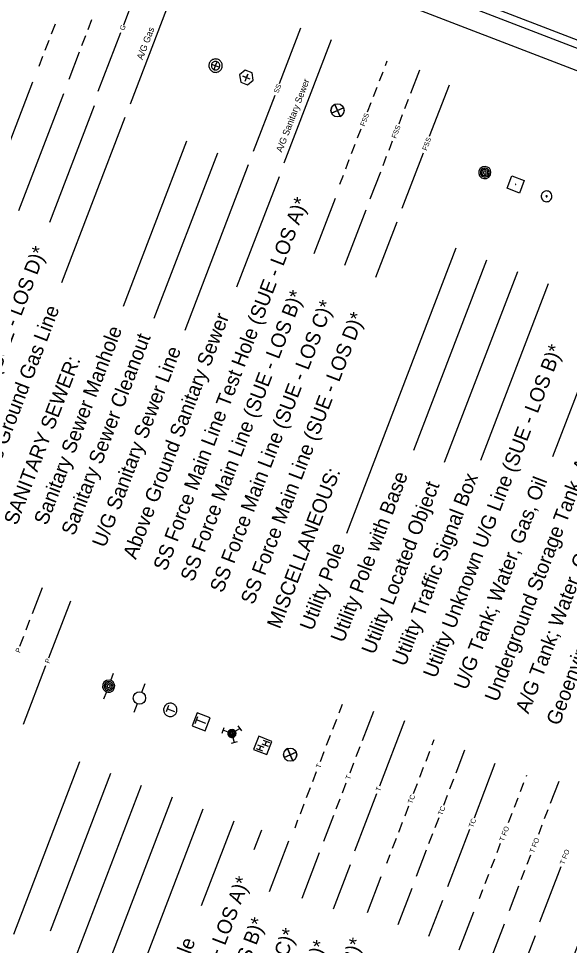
# Model space of a CAD drawing. Extents: x 1015221 to 1064345, y 619216 to 647967.
# Drawn here: x 1051569 to 1054188, y 630539 to 634941 of the extents above; entities that cross this region are included whole.
import ezdxf

# ---------------------------------------------------------------- set-up
doc = ezdxf.new("R2010")
doc.units = 0
for name, color, linetype in [('Default', 7, 'Continuous'), ('Sheet Plot Border Inside CELL', 7, 'Continuous'), ('Sheet Plot Border Outside CELL', 7, 'Continuous'), ('Sheet Symbology CELL', 7, 'Continuous')]:
    doc.layers.add(name, color=color, linetype=linetype)

msp = doc.modelspace()

# ---------------------------------------------------------------- linework, layer by layer
at = {"layer": 'Default'}
for p, q in [((1052069.1, 634911.4), (1052172.7, 635181.1)), ((1052100.4, 634536.4), (1052325.5, 635122.3)), ((1051899.7, 634889.2), (1051918, 634936.8)), ((1051725.7, 634867.8), (1051744, 634915.4)), ((1052809.1, 634632.2), (1052911, 634897.4)), ((1051696.2, 634790.9), (1051714.5, 634838.5)), ((1051870.2, 634812.3), (1051888.5, 634859.9)), ((1051947.5, 634595.1), (1052055, 634874.8)), ((1052831.3, 634255.6), (1053056.4, 634841.5)), ((1051666.6, 634714), (1051684.9, 634761.6)), ((1051809.2, 634653.5), (1051858.9, 634783)), ((1052486.7, 634724.2), (1052524.3, 634709.8)), ((1052498.3, 634698.2), (1052505.5, 634717)), ((1052504.6, 634714.6), (1052504.7, 634714.8)), ((1052505.5, 634717), (1052512.7, 634735.8)), ((1053312.6, 634717.7), (1053321.1, 634739.8)), ((1053284.4, 634644.4), (1053301.3, 634688.4)), ((1053433.9, 634587), (1053476, 634696.7)), ((1051635.6, 634639.2), (1051422.5, 634084.5)), ((1053522.8, 634381.4), (1053616.9, 634626.2)), ((1051782.1, 634582.9), (1051568.9, 634028.2)), ((1052685.9, 634311.5), (1052788, 634577.2)), ((1053256.3, 634571.2), (1053273.2, 634615.1)), ((1053228.1, 634498), (1053245, 634541.9)), ((1053405.7, 634513.8), (1053422.6, 634557.7)), ((1051928.6, 634526.7), (1051715.4, 633971.9)), ((1053377.6, 634440.5), (1053394.5, 634484.5)), ((1052075, 634470.4), (1051773.3, 633685)), ((1053180.3, 634373.5), (1053197.2, 634417.4)), ((1052367.6, 634358), (1052065.8, 633572.6)), ((1053329.8, 634316), (1053346.6, 634360)), ((1053152.2, 634300.2), (1053169, 634344.2)), ((1052514.1, 634301.7), (1052212.3, 633516.3)), ((1053124, 634227), (1053140.9, 634270.9)), ((1053301.6, 634242.8), (1053318.5, 634286.7)), ((1053391.8, 634040.3), (1053493, 634303.7)), ((1052660.5, 634245.4), (1052358.8, 633460)), ((1052807, 634189.2), (1052605.4, 633664.4)), ((1053095.9, 634153.9), (1053112.8, 634197.7)), ((1053241, 634085.1), (1053290.4, 634213.5)), ((1053073.6, 634086.8), (1052972.4, 633823.5)), ((1053220, 634030.5), (1053118.9, 633767.3)), ((1053366.5, 633974.2), (1053265.4, 633711)), ((1053647.3, 633850.3), (1053127, 632495.9)), ((1053793.8, 633794), (1053446.1, 632889.2)), ((1053940.3, 633737.7), (1053592.6, 632832.9)), ((1054086.7, 633681.4), (1053764.1, 632841.5)), ((1054379.7, 633568.9), (1054106.9, 632858.7)), ((1051634.6, 632114.8), (1051682.5, 632239.5)), ((1051713.5, 631905.4), (1051817.4, 632175.7)), ((1051605.1, 632037.9), (1051623.4, 632085.5)), ((1051575.5, 631961), (1051593.8, 632008.6)), ((1051592.2, 631589.8), (1051699.4, 631868.7)), ((1052007.6, 631797.4), (1052021.1, 631832.6)), ((1052154.5, 631741.8), (1052170.3, 631783)), ((1051986.9, 631743.3), (1051973.4, 631708.2)), ((1052133.4, 631686.9), (1052117.5, 631645.7)), ((1052282.3, 631678.3), (1052270.7, 631648.1)), ((1053092.5, 631643.5), (1053108.1, 631684.4)), ((1052276.4, 631663.1), (1052309.7, 631650.3)), ((1052408, 631592.9), (1052421.2, 631627.2)), ((1053203.5, 631512.6), (1053257.1, 631652.1)), ((1052458.8, 631593.1), (1052414.6, 631610)), ((1052611.7, 631582.3), (1052628.2, 631557.9)), ((1053062.9, 631566.6), (1053081.2, 631614.2)), ((1053286.1, 631297.6), (1053405.4, 631608)), ((1052536.5, 631547.5), (1052547, 631574.9)), ((1052565.2, 631552.2), (1052541.7, 631561.2)), ((1052599.1, 631556.1), (1052620, 631570.1)), ((1053033.4, 631489.7), (1053051.7, 631537.3)), ((1052608.2, 631505.8), (1052579.6, 631498.7)), ((1052587.8, 631526.6), (1052593.9, 631502.2)), ((1052705.4, 631491.9), (1052734.9, 631480.6)), ((1052725.8, 631497), (1052755.3, 631485.7)), ((1052732.3, 631513.9), (1052761.8, 631502.6)), ((1052740.8, 631491.3), (1052747.3, 631508.1)), ((1053535.3, 631491.6), (1053544.9, 631516.6)), ((1052698.9, 631475.1), (1052728.4, 631463.7)), ((1052713.9, 631469.3), (1052720.4, 631486.1)), ((1053003.8, 631412.8), (1053022.1, 631460.4)), ((1053174, 631435.7), (1053192.3, 631483.3)), ((1053505.7, 631414.7), (1053524, 631462.3)), ((1053649.1, 631359.6), (1053690.9, 631468.5)), ((1051859.3, 631411.4), (1051544.5, 630591.9)), ((1053144.5, 631358.8), (1053162.7, 631406.4)), ((1053735.4, 631145.7), (1053835.1, 631405.1)), ((1052967.5, 631318.4), (1052985.8, 631366)), ((1053476.2, 631337.8), (1053494.5, 631385.4)), ((1052005.8, 631355.1), (1051718.6, 630607.6)), ((1053619.5, 631282.7), (1053637.8, 631330.3)), ((1053982.5, 631342.9), (1053984.4, 631347.7)), ((1054097.7, 631214.6), (1054138, 631319.4)), ((1052152.3, 631298.8), (1051764.4, 630289.1)), ((1052938, 631241.4), (1052956.3, 631289.1)), ((1053108.2, 631264.3), (1053126.4, 631311.9)), ((1053446.6, 631260.9), (1053464.9, 631308.5)), ((1053954.4, 631269.6), (1053971.3, 631313.6)), ((1052298.8, 631242.6), (1051912.8, 630238)), ((1053078.6, 631187.4), (1053096.9, 631235)), ((1053167.6, 630989.1), (1053272.1, 631261)), ((1053590, 631205.8), (1053608.3, 631253.4)), ((1053926.2, 631196.4), (1053943.1, 631240.3)), ((1052445.3, 631186.3), (1052092.9, 630269.1)), ((1052908.4, 631164.5), (1052926.7, 631212.2)), ((1053405.8, 631154.7), (1053424.1, 631202.3)), ((1054069.5, 631141.3), (1054086.4, 631185.3)), ((1053020.1, 631035.2), (1053067.3, 631158.1)), ((1053549.2, 631099.6), (1053567.5, 631147.2)), ((1053898.1, 631123.1), (1053915, 631167.1)), ((1052591.7, 631130), (1052436.9, 630726.9)), ((1052883, 631098.4), (1052897.2, 631135.2)), ((1053376.3, 631077.8), (1053394.6, 631125.4)), ((1054041.4, 631068.1), (1054058.3, 631112)), ((1052723.5, 631086.3), (1052687.9, 630993.6)), ((1053519.6, 631022.7), (1053537.9, 631070.3)), ((1053610, 630819.2), (1053714.3, 631090.8)), ((1052851.8, 631034.7), (1052759.6, 630794.6)), ((1053346.7, 631000.9), (1053365, 631048.5)), ((1053843.2, 630980.3), (1053860.1, 631024.3)), ((1052998.3, 630978.4), (1052914.9, 630761.4)), ((1053319.8, 630930.6), (1053335.5, 630971.6)), ((1053460.4, 630868.6), (1053508.4, 630993.4)), ((1053986.5, 630925.3), (1054003.4, 630969.2)), ((1053144.8, 630922.1), (1053063.6, 630710.8)), ((1053815.1, 630907.1), (1053832, 630951)), ((1053787, 630833.8), (1053803.8, 630877.8)), ((1053958.4, 630852), (1053975.3, 630896)), ((1054046.6, 630651.4), (1054147.6, 630914.1)), ((1053291.3, 630865.8), (1053225.2, 630694)), ((1053437.8, 630809.6), (1053371.7, 630637.7)), ((1053759.3, 630761.8), (1053775.7, 630804.5)), ((1053902.1, 630705.4), (1053947.1, 630822.7)), ((1053584.2, 630753.3), (1053518.2, 630581.4)), ((1053730.7, 630697), (1053661.4, 630516.6)), ((1053877.2, 630640.7), (1053807.9, 630460.4)), ((1054023.7, 630584.4), (1053954.4, 630404.1))]:
    msp.add_line(p, q, dxfattribs=at)
for points in [[(1052475.8, 634728.4), (1052474.5, 634724.5), (1052473.9, 634720.7), (1052473.7, 634716.6), (1052474.1, 634712.7), (1052474.8, 634708.8), (1052476.1, 634705.1), (1052477.9, 634701.4), (1052480, 634698.1), (1052482.5, 634694.9), (1052485.7, 634692.4), (1052488.9, 634690.1), (1052492.3, 634688.2), (1052496.1, 634686.8), (1052499.8, 634685.9), (1052504, 634685.3), (1052507.8, 634685.2), (1052511.8, 634685.9), (1052515.5, 634686.9), (1052519.4, 634688.4), (1052522.8, 634690.4), (1052525.9, 634692.7), (1052528.9, 634695.4), (1052531.4, 634698.5), (1052533.6, 634702.1), (1052535.2, 634705.6), (1052536.4, 634709.5), (1052537.1, 634713.3), (1052537.3, 634717.3), (1052536.9, 634721.3), (1052536.2, 634725.1), (1052534.9, 634728.9), (1052533.1, 634732.6), (1052531, 634735.8), (1052528.4, 634739), (1052525.3, 634741.6), (1052522.1, 634743.9), (1052518.7, 634745.7), (1052514.9, 634747.2), (1052511.2, 634748.1), (1052507, 634748.6), (1052503.2, 634748.7), (1052499.1, 634748.1), (1052495.5, 634747), (1052491.6, 634745.5), (1052488.1, 634743.6), (1052485, 634741.2), (1052482.1, 634738.5), (1052479.5, 634735.4), (1052477.4, 634731.9), (1052475.8, 634728.4)], [(1052486.7, 634724.2), (1052485.7, 634721), (1052485.4, 634717.9), (1052485.5, 634714.6), (1052486.2, 634711.6), (1052487.2, 634708.4), (1052488.8, 634705.6), (1052490.9, 634703.2), (1052493.3, 634700.9), (1052496, 634699.3), (1052499, 634697.9), (1052502.3, 634697.2), (1052505.4, 634696.8), (1052508.8, 634697.1), (1052511.8, 634697.9), (1052514.8, 634699.2), (1052517.6, 634700.9), (1052520, 634702.9), (1052522.1, 634705.4), (1052523.7, 634708.3), (1052524.8, 634711.2), (1052525.5, 634714.5), (1052525.7, 634717.7), (1052525.3, 634720.8), (1052524.3, 634724), (1052523, 634726.9), (1052521.2, 634729.5), (1052518.9, 634732), (1052516.3, 634733.8), (1052513.4, 634735.5), (1052510.2, 634736.5), (1052507.2, 634737.1), (1052503.9, 634737), (1052500.7, 634736.6), (1052497.6, 634735.6), (1052494.8, 634733.9), (1052492.2, 634732.2), (1052489.9, 634729.8), (1052488.1, 634727.2), (1052486.7, 634724.2)], [(1052684.4, 634648.2), (1052679.2, 634682.7), (1052646.5, 634695.3), (1052619.5, 634673.2), (1052625, 634638.6), (1052657.5, 634626.1), (1052684.4, 634648.2)], [(1052645.6, 634644.1), (1052658.4, 634677.3), (1052652, 634660.7), (1052635.4, 634667.1), (1052668.6, 634654.3)], [(1053072.5, 634533.3), (1053097.9, 634476), (1053085.2, 634504.6), (1053056.6, 634491.9), (1053113.9, 634517.4)], [(1053056.6, 634491.9), (1053085.2, 634504.6), (1053072.5, 634533.3)], [(1053113.9, 634517.4), (1053085.2, 634504.6), (1053097.9, 634476)], [(1053792.9, 634229.2), (1053787.8, 634230.6), (1053782.9, 634230.6), (1053778.1, 634229.4), (1053773.6, 634227.3), (1053769.9, 634224.4), (1053767, 634219.9), (1053764.8, 634215.8), (1053764, 634210.6), (1053764, 634205.6), (1053765.4, 634201.3), (1053768, 634196.6), (1053770.9, 634193), (1053775.4, 634190), (1053779.7, 634188.4), (1053785, 634187.6), (1053789.6, 634188.3), (1053794.6, 634190.1), (1053798.6, 634192.3), (1053801.9, 634196), (1053804.8, 634200.5), (1053805.9, 634205), (1053806.7, 634210.3), (1053806, 634214.9), (1053804, 634219.4), (1053801.3, 634223.5), (1053797.6, 634226.8), (1053792.9, 634229.2)], [(1053790.4, 634222.7), (1053786.4, 634223.7), (1053782, 634223.5), (1053778.3, 634221.8), (1053774.9, 634219.4), (1053772.5, 634216.6), (1053770.9, 634212.3), (1053770.7, 634208.6), (1053771.6, 634204.5), (1053773.3, 634200.8), (1053776.4, 634197.7), (1053780, 634195.7), (1053784, 634194.8), (1053788.4, 634195), (1053792.2, 634196.6), (1053795.6, 634199), (1053797.9, 634201.9), (1053799.6, 634206.2), (1053799.7, 634209.9), (1053798.8, 634213.9), (1053797.1, 634217.7), (1053794, 634220.8), (1053790.4, 634222.7)], [(1053787.7, 634215.7), (1053784.8, 634216.2), (1053782, 634215.4), (1053780.1, 634213.7), (1053778.5, 634211.2), (1053778.6, 634208.1), (1053779.3, 634205.3), (1053781.6, 634203.2), (1053783.8, 634202.3), (1053786.9, 634202.4), (1053789.4, 634203.9), (1053791.5, 634206.2), (1053792, 634209.1), (1053791.7, 634211.7), (1053790.2, 634214.1), (1053787.7, 634215.7)], [(1053890.8, 634134.5), (1053913.5, 634193.8), (1053972.8, 634171), (1053950, 634111.7), (1053890.8, 634134.5)], [(1053931, 634152.9), (1053931.2, 634152.5), (1053931.8, 634152.3), (1053932.6, 634152.6), (1053932.5, 634153.3), (1053932, 634153.8), (1053931.2, 634153.5), (1053931, 634152.9)], [(1054087.8, 634120.3), (1054082.9, 634121.6), (1054077.6, 634122), (1054072.4, 634121.3), (1054067.7, 634119.3), (1054063.4, 634116.5), (1054059.4, 634113.2), (1054056.8, 634109.3), (1054054.3, 634104.2), (1054053.4, 634099.1), (1054053.2, 634094.3), (1054054, 634089.1), (1054056, 634084.4), (1054059.2, 634079.9), (1054062.8, 634076.4), (1054067.1, 634073.6), (1054071.9, 634071.8), (1054077, 634070.9), (1054082, 634071.2), (1054087.4, 634072.4), (1054092, 634074.4), (1054096.1, 634077.8), (1054099.1, 634081.5), (1054101.9, 634085.9), (1054103.4, 634091.3), (1054104.1, 634096), (1054103.4, 634101.2), (1054102, 634106.1), (1054099.9, 634110.7), (1054096.6, 634114.7), (1054092.4, 634118), (1054087.8, 634120.3)], [(1054076.2, 634098.5), (1054075.6, 634097.1), (1054076, 634095.3), (1054077.1, 634093.8), (1054078.7, 634093.7), (1054080.5, 634094.1), (1054081.5, 634095.4), (1054081.6, 634097), (1054081, 634098.3), (1054079.3, 634099.5), (1054077.7, 634099.6), (1054076.2, 634098.5)], [(1052004.9, 631790.4), (1051999.9, 631791.7), (1051994.9, 631791.8), (1051990.1, 631790.5), (1051985.6, 631788.5), (1051982, 631785.6), (1051979, 631781.1), (1051976.8, 631777), (1051976, 631771.7), (1051976, 631766.8), (1051977.5, 631762.5), (1051980, 631757.8), (1051983, 631754.2), (1051987.4, 631751.2), (1051991.7, 631749.5), (1051997, 631748.8), (1052001.6, 631749.5), (1052006.7, 631751.3), (1052010.6, 631753.5), (1052013.9, 631757.2), (1052016.8, 631761.6), (1052018, 631766.1), (1052018.8, 631771.4), (1052018, 631776), (1052016, 631780.5), (1052013.3, 631784.7), (1052009.6, 631788), (1052004.9, 631790.4)], [(1052002.4, 631783.9), (1051998.4, 631784.8), (1051994, 631784.6), (1051990.3, 631783), (1051986.9, 631780.6), (1051984.6, 631777.7), (1051982.9, 631773.4), (1051982.7, 631769.7), (1051983.6, 631765.7), (1051985.3, 631761.9), (1051988.5, 631758.9), (1051992.1, 631756.9), (1051996.1, 631756), (1052000.4, 631756.1), (1052004.2, 631757.8), (1052007.6, 631760.2), (1052009.9, 631763), (1052011.6, 631767.4), (1052011.8, 631771), (1052010.8, 631775.1), (1052009.2, 631778.8), (1052006, 631781.9), (1052002.4, 631783.9)], [(1051999.7, 631776.9), (1051996.8, 631777.4), (1051994, 631776.6), (1051992.1, 631774.8), (1051990.6, 631772.3), (1051990.6, 631769.2), (1051991.4, 631766.4), (1051993.7, 631764.3), (1051995.8, 631763.5), (1051999, 631763.5), (1052001.4, 631765.1), (1052003.5, 631767.4), (1052004, 631770.3), (1052003.8, 631772.8), (1052002.2, 631775.3), (1051999.7, 631776.9)], [(1052260.5, 631669.2), (1052259.3, 631665.4), (1052258.6, 631661.5), (1052258.4, 631657.5), (1052258.8, 631653.5), (1052259.5, 631649.7), (1052260.8, 631645.9), (1052262.6, 631642.2), (1052264.7, 631639), (1052267.3, 631635.8), (1052270.4, 631633.2), (1052273.6, 631630.9), (1052277, 631629.1), (1052280.8, 631627.6), (1052284.5, 631626.7), (1052288.7, 631626.2), (1052292.5, 631626.1), (1052296.6, 631626.7), (1052300.2, 631627.8), (1052304.1, 631629.3), (1052307.6, 631631.2), (1052310.7, 631633.6), (1052313.6, 631636.3), (1052316.2, 631639.4), (1052318.3, 631642.9), (1052319.9, 631646.4), (1052321.2, 631650.3), (1052321.8, 631654.1), (1052322, 631658.2), (1052321.6, 631662.1), (1052320.9, 631666), (1052319.6, 631669.7), (1052317.8, 631673.4), (1052315.8, 631676.7), (1052313.2, 631679.9), (1052310, 631682.4), (1052306.8, 631684.7), (1052303.5, 631686.6), (1052299.6, 631688.1), (1052295.9, 631689), (1052291.7, 631689.5), (1052287.9, 631689.6), (1052283.9, 631688.9), (1052280.2, 631687.9), (1052276.3, 631686.4), (1052272.9, 631684.4), (1052269.8, 631682.1), (1052266.8, 631679.4), (1052264.3, 631676.3), (1052262.1, 631672.7), (1052260.5, 631669.2)], [(1052455.7, 631558.9), (1052479.4, 631620.5), (1052417.7, 631644.2), (1052394, 631582.6), (1052455.7, 631558.9)], [(1052588.3, 631558.6), (1052584.9, 631559.5), (1052581.6, 631559.5), (1052578.4, 631558.7), (1052575.4, 631557.3), (1052573, 631555.4), (1052571, 631552.4), (1052569.6, 631549.7), (1052569, 631546.1), (1052569, 631542.8), (1052570, 631540), (1052571.7, 631536.9), (1052573.7, 631534.4), (1052576.6, 631532.5), (1052579.5, 631531.4), (1052583, 631530.8), (1052586.1, 631531.3), (1052589.5, 631532.5), (1052592.1, 631534), (1052594.3, 631536.5), (1052596.2, 631539.4), (1052597, 631542.4), (1052597.5, 631546), (1052597, 631549), (1052595.7, 631552), (1052593.9, 631554.8), (1052591.4, 631557), (1052588.3, 631558.6)], [(1052586.6, 631554.3), (1052584, 631554.9), (1052581.1, 631554.8), (1052578.5, 631553.7), (1052576.3, 631552.1), (1052574.7, 631550.2), (1052573.6, 631547.3), (1052573.5, 631544.8), (1052574.1, 631542.1), (1052575.2, 631539.6), (1052577.3, 631537.6), (1052579.7, 631536.3), (1052582.4, 631535.6), (1052585.3, 631535.8), (1052587.8, 631536.9), (1052590.1, 631538.5), (1052591.6, 631540.4), (1052592.7, 631543.2), (1052592.9, 631545.7), (1052592.3, 631548.4), (1052591.1, 631550.9), (1052589, 631552.9), (1052586.6, 631554.3)], [(1052584.8, 631549.6), (1052582.9, 631549.9), (1052581.1, 631549.4), (1052579.8, 631548.2), (1052578.7, 631546.6), (1052578.7, 631544.5), (1052579.3, 631542.6), (1052580.8, 631541.2), (1052582.2, 631540.7), (1052584.3, 631540.7), (1052586, 631541.7), (1052587.4, 631543.2), (1052587.7, 631545.2), (1052587.5, 631546.9), (1052586.5, 631548.5), (1052584.8, 631549.6)], [(1052749.1, 631445.3), (1052773.3, 631508.4), (1052710.3, 631532.6), (1052686, 631469.6), (1052749.1, 631445.3)], [(1052847, 631473.7), (1052872.5, 631416.4), (1052859.8, 631445.1), (1052831.1, 631432.3), (1052888.4, 631457.8)], [(1052831.1, 631432.3), (1052859.8, 631445.1), (1052847, 631473.7)], [(1052888.4, 631457.8), (1052859.8, 631445.1), (1052872.5, 631416.4)]]:
    msp.add_lwpolyline(points, dxfattribs=at)
for points in [[(1053812.3, 634198.8), (1053814.5, 634211), (1053812, 634220.7), (1053806.7, 634229.5), (1053797.2, 634235.6), (1053787.1, 634238.3), (1053775.3, 634236.6), (1053763, 634228.9), (1053757.1, 634216.9), (1053756.2, 634204.9), (1053760.5, 634193.3), (1053769.1, 634185), (1053781, 634180.5), (1053792.9, 634180.8), (1053804.8, 634187.4)], [(1052024.3, 631760), (1052026.5, 631772.2), (1052024, 631781.8), (1052018.7, 631790.7), (1052009.3, 631796.8), (1051999.1, 631799.5), (1051987.3, 631797.8), (1051975, 631790.1), (1051969.2, 631778.1), (1051968.3, 631766), (1051972.5, 631754.5), (1051981.1, 631746.2), (1051993, 631741.6), (1052004.9, 631742), (1052016.8, 631748.6)], [(1052601.2, 631538.3), (1052602.7, 631546.5), (1052601, 631552.9), (1052597.5, 631558.8), (1052591.2, 631562.9), (1052584.4, 631564.6), (1052576.6, 631563.5), (1052568.4, 631558.4), (1052564.5, 631550.4), (1052563.9, 631542.4), (1052566.7, 631534.6), (1052572.4, 631529.1), (1052580.4, 631526.1), (1052588.3, 631526.3), (1052596.2, 631530.7)]]:
    msp.add_lwpolyline(points, close=True, dxfattribs=at)
for centre, radius in [((1053085.2, 634504.6), 31.4), ((1052143.7, 631714.1), 29.4), ((1052859.8, 631445.1), 31.4)]:
    msp.add_circle(centre, radius, dxfattribs=at)
for centre, start, end in [((1053085.2, 634504.6), 113.983, 203.983), ((1053085.2, 634504.6), 293.983, 23.983), ((1052859.8, 631445.1), 113.983, 203.983), ((1052859.8, 631445.1), 293.983, 23.983)]:
    msp.add_arc(centre, 31.4, start, end, dxfattribs=at)
at = {"layer": 'Sheet Plot Border Inside CELL'}
msp.add_lwpolyline([(1050898.2, 621795.3), (1055679.6, 634240.3), (1047800.3, 637267.6), (1043018.9, 624822.5)], close=True, dxfattribs=at)
at = {"layer": 'Sheet Plot Border Outside CELL'}
msp.add_lwpolyline([(1051028.5, 621633.8), (1055860.2, 634209.5), (1047645.6, 637365.6), (1042813.9, 624789.8)], close=True, dxfattribs=at)
at = {"layer": 'Sheet Symbology CELL'}
msp.add_lwpolyline([(1047783.5, 637166.9), (1043479.8, 625965.2), (1051313.4, 622955.5), (1055617.1, 634157.2)], close=True, dxfattribs=at)

# ---------------------------------------------------------------- texts
at = {"layer": 'Default'}
for s, height, p in [('G', 23.5, (1052070.5, 634882.3)), ('A/G Gas', 31.38, (1052158.3, 634742.6)), ('SS', 23.54, (1052803.1, 634583.6)), ('A/G Sanitary Sewer', 31.385, (1052820.7, 634302.9)), ('FSS', 23.54, (1053213.4, 634426.7)), ('FSS', 23.54, (1053362.8, 634369.3)), ('FSS', 23.54, (1053508.6, 634311.6)), ('SS Force Main Line Test Hole (SUE - LOS A)*', 68.654, (1052270.7, 632313.3)), ('U/G Gas Line (SUE - LOS D)*', 68.654, (1051264.8, 632699.7)), ('SS Force Main Line (SUE - LOS B)*', 68.654, (1052399.7, 632262.4)), ('SS Force Main Line (SUE - LOS C)*', 68.654, (1052539.8, 632209.9)), ('Above Ground Gas Line', 68.654, (1051411.3, 632643.4)), ('Above Ground Sanitary Sewer', 68.654, (1052126.7, 632368.6)), ('SS Force Main Line (SUE - LOS D)*', 68.654, (1052686.3, 632153.6)), ('Sanitary Sewer Manhole', 68.654, (1051703.8, 632531)), ('Sanitary Sewer Cleanout', 68.654, (1051833.8, 632481.1)), ('Utility Unknown U/G Line (SUE - LOS B)*', 68.654, (1053553, 631804.5)), ('U/G Sanitary Sewer Line', 68.654, (1051980.3, 632424.8)), ('SANITARY SEWER:', 68.654, (1051561, 632531.1)), ('Underground Storage Tank, Approx. Loc.', 68.654, (1053845.9, 631691.9)), ('MISCELLANEOUS:', 68.654, (1052811.2, 632038.6)), ('Utility Pole with Base', 68.654, (1053113.5, 631973.3)), ('Utility Traffic Signal Box', 68.654, (1053406.5, 631860.8)), ('U/G Tank; Water, Gas, Oil', 68.654, (1053699.4, 631748.2)), ('Utility Located Object', 68.654, (1053260, 631917.1)), ('A/G Tank; Water, Gas, Oil', 68.654, (1053992.4, 631635.7)), ('Geoenvironmental Boring', 68.654, (1054138.9, 631579.4)), ('Utility Pole', 68.654, (1052967, 632029.6)), ('P', 23.5, (1051575, 631926.7)), ('P', 23.5, (1051714.9, 631876.2)), ('T', 23.5, (1053003.1, 631378.2)), ('T', 23.5, (1053143.8, 631324.2)), ('T', 23.5, (1053287.4, 631268.2)), ('TC', 23.54, (1053439.6, 631209.8)), ('TC', 23.54, (1053583, 631154.7)), ('TC', 23.54, (1053729.1, 631096.5)), ('T FO', 23.54, (1053875.3, 631031)), ('T FO', 23.54, (1054018.6, 630976)), ('T FO', 23.54, (1054162.8, 630920.9)), ('U/G Telephone Test Hole (SUE - LOS A)*', 68.654, (1052059.7, 629259.3)), ('U/G Telephone Cable (SUE - LOS B)*', 68.654, (1052188, 629207.7)), ('U/G Telephone Cable (SUE - LOS C)*', 68.654, (1052334.5, 629151.4)), ('U/G Telephone Cable Hand Hole', 68.654, (1051928, 629303)), ('U/G Telephone Conduit (SUE - LOS B)*', 68.654, (1052627.5, 629038.9)), ('U/G Telephone Cable (SUE - LOS D)*', 68.654, (1052481, 629095.1))]:
    msp.add_text(s, height=height, rotation=68.983, dxfattribs=at).set_placement(p)

doc.saveas('drawing.dxf')
